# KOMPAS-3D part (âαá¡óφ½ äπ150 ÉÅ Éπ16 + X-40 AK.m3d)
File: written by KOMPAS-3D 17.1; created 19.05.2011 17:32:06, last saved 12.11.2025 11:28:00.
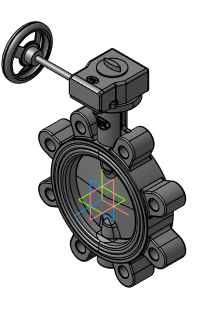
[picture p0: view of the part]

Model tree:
1. Плоскость XY
2. Плоскость ZX
3. Плоскость ZY
4. Ось X
5. Ось Y
6. Ось Z
7. Начало координат
8. Операция без истории:5

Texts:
  Viktor2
